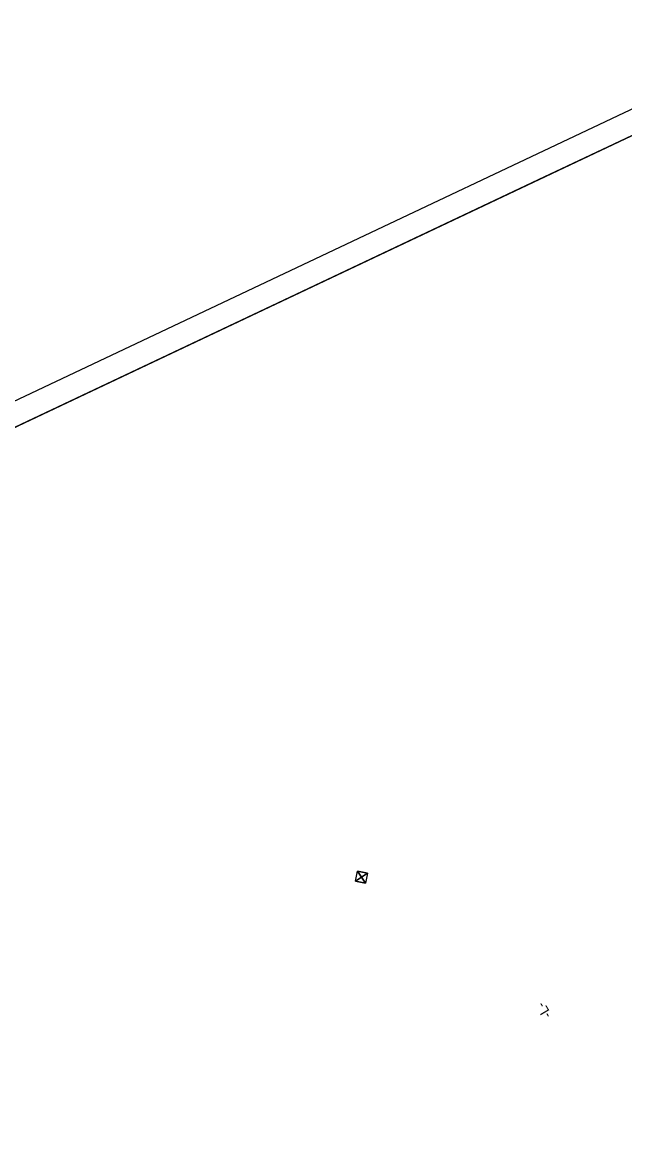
# Model space of a CAD drawing. Extents: x 476855 to 478565, y 498324 to 500313.
# Drawn here: x 477283 to 477710, y 499525 to 500313 of the extents above; entities that cross this region are included whole.
import ezdxf

# ---------------------------------------------------------------- set-up
doc = ezdxf.new("R2010")
doc.units = 0
for name, color, linetype in [('Default', 7, 'Continuous'), ('Prop Horizontal Alignment Direction Label', 7, 'Continuous'), ('Sheet Layout Plan Border', 7, 'Continuous'), ('Sheet Plan CELL', 7, 'Continuous'), ('Sheet Plot Border Outside CELL', 7, 'Continuous')]:
    doc.layers.add(name, color=color, linetype=linetype)

msp = doc.modelspace()

# ---------------------------------------------------------------- linework, layer by layer
at = {"layer": 'Default'}
msp.add_line((477523.23, 499707.46), (477523.23, 499707.46), dxfattribs=at)
msp.add_lwpolyline([(477520.36, 499711.65), (477527.42, 499710.33), (477526.1, 499703.26), (477519.03, 499704.59)], close=True, dxfattribs=at)
for points in [[(477527.42, 499710.33), (477519.03, 499704.59), (477523.23, 499707.46), (477526.1, 499703.26), (477520.36, 499711.65)], [(477523.23, 499707.46), (477527.42, 499710.33), (477520.36, 499711.65), (477523.23, 499707.46)], [(477523.23, 499707.46), (477519.03, 499704.59), (477526.1, 499703.26), (477523.23, 499707.46)]]:
    msp.add_lwpolyline(points, dxfattribs=at)
at = {"layer": 'Sheet Layout Plan Border'}
msp.add_lwpolyline([(478473.37, 498931.82), (477903.68, 500137.33), (477832.75, 500100.13), (477759.99, 500254.29), (477648.51, 500201.67), (477648.51, 500201.67), (477181.74, 499981.09), (477039.82, 499914.02), (477125.29, 499733.16), (477006.1, 499676.83), (477073.33, 499534.55), (477035.61, 499516.73), (477523.84, 498483.65)], close=True, dxfattribs=at)
at = {"layer": 'Sheet Plan CELL'}
for points in [[(476882.9, 499839.89), (477523.8, 498483.67), (478473.14, 498932.29), (477832.24, 500288.49)], [(478473.17, 498932.3), (477523.84, 498483.65), (476968.37, 499659.01), (477104.04, 499723.12), (477018.58, 499903.99), (477832.24, 500288.49)]]:
    msp.add_lwpolyline(points, close=True, dxfattribs=at)
at = {"layer": 'Sheet Plot Border Outside CELL'}
msp.add_lwpolyline([(477845.33, 500313.48), (478564.63, 498791.38), (477574.61, 498323.53), (476855.31, 499845.63)], close=True, dxfattribs=at)

# ---------------------------------------------------------------- texts
at = {"layer": 'Prop Horizontal Alignment Direction Label'}
msp.add_text('-L-', height=7, rotation=120.8092, dxfattribs=at).set_placement((477658.4, 499609.77))

doc.saveas('drawing.dxf')
